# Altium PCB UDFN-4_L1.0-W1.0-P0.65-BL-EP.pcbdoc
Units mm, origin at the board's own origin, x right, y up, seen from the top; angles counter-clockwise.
Board outline 14.02 x 14.28 mm, 2 copper layers (Top Layer, Bottom Layer), stack 0 mm thick; 1 components, 0 nets, 5 pads, 0 vias.
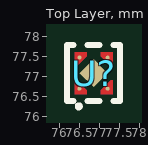
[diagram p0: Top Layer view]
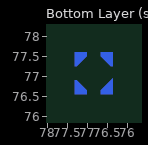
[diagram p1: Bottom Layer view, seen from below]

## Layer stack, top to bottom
Top Layer: signal copper (thickness not stored)
Bottom Layer: signal copper (thickness not stored)

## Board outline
83.87,69.85 69.85,69.85 69.85,84.13 83.87,84.13

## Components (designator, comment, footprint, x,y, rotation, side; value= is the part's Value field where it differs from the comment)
U? "" UDFN-4_L1.0-W1.0-P0.65-BL-EP 76.86,77.08 r0 top

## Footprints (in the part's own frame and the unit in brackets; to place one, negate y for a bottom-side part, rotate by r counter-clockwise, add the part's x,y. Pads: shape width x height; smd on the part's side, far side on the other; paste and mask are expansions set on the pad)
UDFN-4_L1.0-W1.0-P0.65-BL-EP [mm]
  round 0.099 smd: 1(-0.355,-0.385)
  round 0.101 smd: 2(0.353,-0.389)
  round 0.1 smd: 3(0.353,0.389) 4(-0.353,0.389)
  rect 0.5x0.5 smd rot 45: 5(0,0)
  Top Layer region: -0.175,-0.525 -0.475,-0.525 -0.475,-0.125 -0.175,-0.425
  Top Layer region: 0.175,0.525 0.475,0.525 0.475,0.175 0.425,0.175 0.175,0.425
  Top Layer region: -0.475,0.175 -0.475,0.525 -0.175,0.525 -0.175,0.475 -0.175,0.425 -0.425,0.175
  Top Layer region: 0.475,-0.175 0.475,-0.525 0.175,-0.525 0.175,-0.425 0.425,-0.175
  Bottom Layer region: -0.175,-0.525 -0.475,-0.525 -0.475,-0.125 -0.175,-0.425
  Bottom Layer region: 0.175,0.525 0.475,0.525 0.475,0.175 0.425,0.175 0.175,0.425
  Bottom Layer region: -0.475,0.175 -0.475,0.525 -0.175,0.525 -0.175,0.475 -0.175,0.425 -0.425,0.175
  Bottom Layer region: 0.475,-0.175 0.475,-0.525 0.175,-0.525 0.175,-0.425 0.425,-0.175
  Multi-Layer region: -0.175,-0.525 -0.475,-0.525 -0.475,-0.125 -0.175,-0.425
  Multi-Layer region: 0.175,0.525 0.475,0.525 0.475,0.175 0.425,0.175 0.175,0.425
  Multi-Layer region: -0.475,0.175 -0.475,0.525 -0.175,0.525 -0.175,0.475 -0.175,0.425 -0.425,0.175
  Multi-Layer region: 0.475,-0.175 0.475,-0.525 0.175,-0.525 0.175,-0.425 0.425,-0.175
  silkscreen extent -0.66,-0.88 0.66,0.7

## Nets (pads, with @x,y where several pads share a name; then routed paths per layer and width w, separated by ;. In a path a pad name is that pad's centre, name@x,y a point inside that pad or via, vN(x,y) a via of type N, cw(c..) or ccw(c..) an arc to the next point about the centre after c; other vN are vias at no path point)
pads on no net: U?.1 U?.2 U?.3 U?.4 U?.5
